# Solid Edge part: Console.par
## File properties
Author: m_hel
Template: Iso Metric Part.par
Last saved by: m_hel
Revision: 14
Application: Solid Edge
Accuracy: 0,990
Username: m_hel
Material: Textured White
Face Style: White painted
Fill Style: ANSI36(Marble)
Virtual Style: ANSI36(Marble)
Grouping: Uncategorized
LibraryName: Custom Materials
Coef. of Thermal Exp: 0.0
Thermal Conductivity: 0.0
Specific Heat: 0.0
Modulus of Elasticity: 0.0
Poisson's Ratio: 0.0
Yield Stress: 0.0
Ultimate Stress: 0.0
Elongation: 0.0
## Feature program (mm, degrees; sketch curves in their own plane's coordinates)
sketch for "unnamed Protrusion 1" plane through (0, 0, 0) normal (0, 0, 1) x-axis (1, 0, 0)
  line (-300, -300) -> (300, -300)
  line (300, -300) -> (300, 300)
  line (300, 300) -> (-300, 300)
  line (-300, 300) -> (-300, -300)
extrude "unnamed Protrusion 1" add finite 1000 along +normal
sketch for "unnamed Cutout 1" plane through (300, 0, 600) normal (1, 0, 0) x-axis (0, 1, 0)
  line (300, -100) -> (-50.1038, 400)
  line (-194.2038, 400) -> (-50.1038, 400)
  line (-194.2038, 400) -> (-300, -200)
extrude "unnamed Cutout 1" cut through along -normal
sketch for "unnamed Cutout 2" plane through (0, -300, 600) normal (0, -1, 0) x-axis (1, 0, 0)
  line (270, -200) -> (270, 400)
  line (300, -200) -> (270, -200)
extrude "unnamed Cutout 2" cut through along -normal
mirror "unnamed Mirror 1" of "unnamed Cutout 2" about plane through (0, 0, 0) normal (1, 0, 0)
extrude "unnamed Cutout 3" cut through
logasc func "Lip_Groove_2"  LipOrGrooveWidth = 20 mm; LipOrGrooveHeight = 50 mm
fillet "Round_22" radius 15
thinwall "Thinwall_1"  Thickness = 10 mm
sketch used by "unnamed Cutout 4" plane through (0, 125.8311, 748.7389) normal (0, 0.819152, 0.573576) x-axis (-1, 0, 0)
extrude "unnamed Cutout 4" cut through along -normal
sketch used by "unnamed Cutout 5" plane through (0, -109.6105, 1000) normal (0, 0, 1) x-axis (-1, 0, 0)
extrude "unnamed Cutout 5" cut through along -normal
mirror "unnamed Mirror 2" of "unnamed Cutout 5" about plane through (0, 0, 0) normal (1, 0, 0)
extrude "unnamed Cutout 6" cut through
sketch used by "unnamed Cutout 7" plane through (0, 125.8311, 748.7389) normal (0, 0.819152, 0.573576) x-axis (-1, 0, 0)
extrude "unnamed Cutout 7" cut through along -normal
sketch for "unnamed Cutout 8" plane through (0, 300, 247.6353) normal (0, 1, 0) x-axis (-1, 0, 0)
  line (-175, -177.6353) -> (175, -177.6353)
  line (175, -177.6353) -> (175, 172.3647)
  line (175, 172.3647) -> (-175, 172.3647)
  line (-175, 172.3647) -> (-175, -177.6353)
  dimension (linear) = 175
  dimension (linear) = 175
extrude "unnamed Cutout 8" cut through along -normal
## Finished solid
Body 1: solid body, 132 faces, 292 edges, 160 vertices.
  Faces by surface: cylinder 57, plane 35, sphere 28, torus 8, blend 4
  Edges by curve: line 144, circle 122, ellipse 24, intersection 2
Bounding box of the edges (mm; curved faces can reach further): 600.000 x 600.000 x 1000.000, from (-300, -300, 0) to (300, 300, 1000).
Cylindrical faces by radius (mm): R5 x25, R15 x27, R25 x3, R40 x2
Toroidal faces (ring radius, tube radius in mm): R30 r5 x4, R30 r15 x4
Spherical faces by radius (mm): R5 x14, R15 x14
Planar faces by outward normal: +x 8, +y 2, +z 3, -x 8, -y 2, -z 4, oblique 8
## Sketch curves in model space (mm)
line (-205, 268.6085, 544.8318) -> (-205, 182.572, 667.7046)
line (-205, 182.572, 667.7046) -> (-125, 182.572, 667.7046)
line (-125, 182.572, 667.7046) -> (-125, 268.6085, 544.8318)
line (-125, 268.6085, 544.8318) -> (-205, 268.6085, 544.8318)
circle centre (105, 153.8932, 708.6622) radius 25
circle centre (175, -109.6105, 1000) radius 40
line (270, -300, 400) -> (270, -300, 1000)
line (300, -300, 400) -> (270, -300, 400)
line (300, 300, 500) -> (300, -50.1038, 1000)
line (300, -194.2038, 1000) -> (300, -300, 400)
line (300, -194.2038, 1000) -> (300, -50.1038, 1000)
line (300, -300, 0) -> (300, 300, 0)
line (300, 300, 0) -> (-300, 300, 0)
line (-300, 300, 0) -> (-300, -300, 0)
line (-300, -300, 0) -> (300, -300, 0)
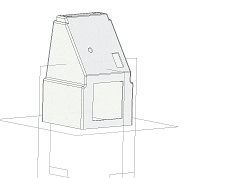
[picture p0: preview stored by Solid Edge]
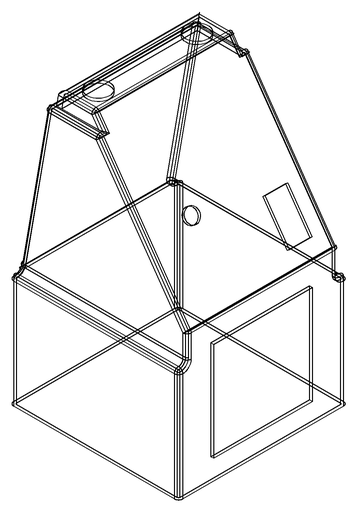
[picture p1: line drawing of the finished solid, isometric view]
